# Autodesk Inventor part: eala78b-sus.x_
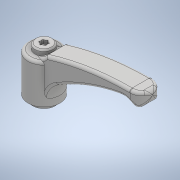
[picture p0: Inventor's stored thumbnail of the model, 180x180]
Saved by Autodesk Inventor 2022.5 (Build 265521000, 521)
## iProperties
Created: 2018-05
Part Number: eala78b-sus.x_
Material: 一般
Document SubType Name: Modeling
Designer: imaocorp
Density: 1 g/cm^3
Appearance: 既定
Sending System: SOLIDWORKS 2016-2016286
MC: AMD64
MC_MODEL: AMD64 Family 21 Model 2 Stepping 0, AuthenticAMD
OS: Windows_NT
FRU: Parasolid Version 28.0, build 224,  7-29-2016
FORMAT: text
GUISE: transmit
KEY: eala78b-sus
FILE: eala78b-sus.x_t
DATE: Fri May 18 11:31:45 2018
Author: imaocorp
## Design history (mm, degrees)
feature "Base1"
node "ソリッド1"
